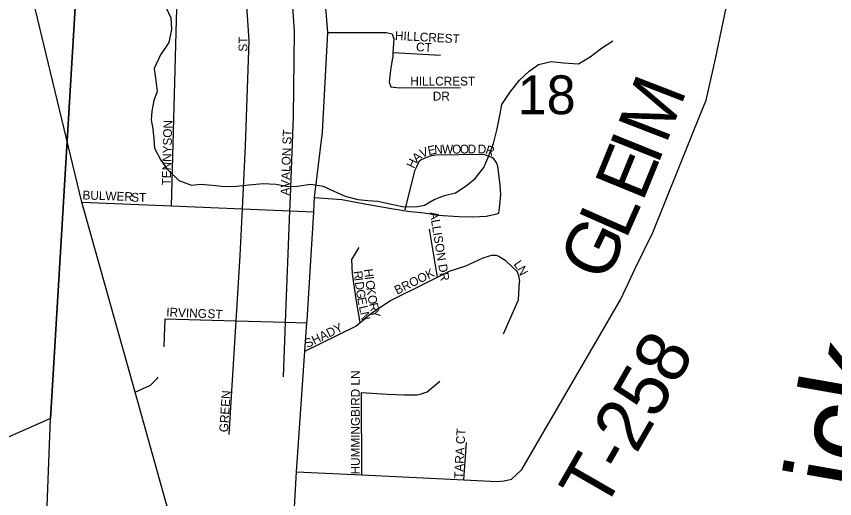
# Model space of a CAD drawing. Extents: x 1624196 to 2029251, y 146837 to 440034.
# Drawn here: x 1866006 to 1870650, y 260043 to 262784 of the extents above; entities that cross this region are included whole.
import ezdxf

# ---------------------------------------------------------------- set-up
doc = ezdxf.new("R2010")
doc.units = 0
for name, color, linetype in [('GM_X_County_Road', 7, 'Continuous'), ('GM_X_Minor_River', 7, 'Continuous'), ('GM_X_Minor_River_Text', 7, 'Continuous'), ('GM_X_Section', 7, 'Continuous'), ('GM_X_Section_Text', 7, 'Continuous'), ('GM_X_Township_Road', 7, 'Continuous'), ('GM_X_Township_Road_Text', 7, 'Continuous'), ('GM_X_Township_Subdivision', 7, 'Continuous'), ('GM_X_Township_Subdivision_Text', 7, 'Continuous')]:
    doc.layers.add(name, color=color, linetype=linetype)

msp = doc.modelspace()

# ---------------------------------------------------------------- linework, layer by layer
at = {"layer": 'GM_X_County_Road'}
for points in [[(1867016.2, 259449.3), (1866680.5, 260648), (1866378.1, 261727.9), (1865950, 263507.3), (1865868, 264025.5), (1865831.5, 264390), (1865827, 264599.6), (1865858.9, 265423.9), (1865861.6, 265586.7)], [(1867547.3, 259323.3), (1867596.2, 260196.4), (1867643.9, 260881.7), (1867655.2, 261043.1), (1867656, 261055.5), (1867693.7, 261672.7), (1867698.7, 261754.4), (1867743.6, 262126.6), (1867774.8, 262693), (1867760, 262854.7), (1867760, 263082.2), (1867749, 263347), (1867728.1, 263652), (1867689.8, 264117.9), (1867679.8, 264316.7), (1867679.8, 264377.8), (1867662.8, 264460.2), (1867586.8, 265007.1), (1867577.4, 265105.3), (1867562.6, 265135)]]:
    msp.add_lwpolyline(points, dxfattribs=at)
at = {"layer": 'GM_X_Minor_River'}
for points in [[(1866855.1, 262835.7), (1866882.6, 262775.5), (1866886.1, 262709.4), (1866871.5, 262635.4), (1866825, 262565.7), (1866788.4, 262487.9), (1866795.9, 262431.8), (1866805.4, 262357.6), (1866787, 262305.7), (1866774.5, 262245.7), (1866772.1, 262195.7), (1866781.7, 262145.6), (1866787.2, 262085.4), (1866790.8, 262035.4), (1866826.3, 261967), (1866861.8, 261914.7), (1866929.3, 261852.1), (1867001, 261825.5), (1867053, 261831.1), (1867118.9, 261824.5), (1867186.8, 261818), (1867254.8, 261819.5), (1867324.8, 261826.9), (1867406.8, 261834.3), (1867478.7, 261829.7), (1867548.6, 261817.2), (1867600.5, 261818.8), (1867676.6, 261830.2), (1867748.4, 261819.6), (1867808.2, 261791.1), (1867871.9, 261762.6), (1867943.7, 261744), (1868001.6, 261737.5), (1868057.5, 261733.1), (1868125.4, 261718.5), (1868197.2, 261703.9), (1868273.1, 261701.3), (1868323.2, 261711), (1868377.4, 261742.6), (1868435.5, 261766.1), (1868497.6, 261781.7), (1868559.9, 261821.2), (1868610.2, 261862.9), (1868658.6, 261924.6), (1868681, 261978.5), (1868713.7, 262062.3), (1868734.3, 262144.2), (1868751, 262230.2), (1868761.4, 262282.2), (1868805.9, 262351.9), (1868862.4, 262421.5), (1868916.8, 262473.1), (1868969, 262510.8), (1869041.1, 262528.2), (1869111, 262519.7), (1869196.9, 262515), (1869263.2, 262554.5), (1869327.5, 262604.1)], [(1869327.5, 262604.1), (1869391.8, 262645.6)]]:
    msp.add_lwpolyline(points, dxfattribs=at)
at = {"layer": 'GM_X_Section'}
msp.add_lwpolyline([(1863140.4, 265454.9), (1866483.9, 265233.4), (1866199.3, 260498.3), (1864651.3, 259815.2)], dxfattribs=at)
msp.add_lwpolyline([(1866483.9, 265233.4), (1871875.5, 264953), (1871606.9, 259505.4), (1866171.2, 259752), (1866199.3, 260498.3)], close=True, dxfattribs=at)
at = {"layer": 'GM_X_Township_Road'}
for points in [[(1868870.9, 260206.2), (1868874.3, 260209.4), (1869435.8, 261176.5), (1869518.9, 261352.1), (1869618.1, 261555.6), (1869894.2, 262242.5), (1869920.6, 262308.4), (1869974.1, 262542.3), (1870339.9, 264293.2), (1870370.3, 264451.8), (1870427.3, 264611.5), (1870634.5, 265099.9)], [(1867596.2, 260196.4), (1867966, 260178.2), (1868546.1, 260149.6), (1868734.1, 260140.4), (1868774, 260144.1), (1868816, 260153.8), (1868870.6, 260205.9), (1868870.9, 260206.2)]]:
    msp.add_lwpolyline(points, dxfattribs=at)
at = {"layer": 'GM_X_Township_Subdivision'}
for points in [[(1867213.3, 260408.5), (1867253.6, 261054.4), (1867276.8, 261425.1), (1867289.7, 261689.6), (1867307.1, 262048), (1867326.9, 262644.9), (1867301.3, 263047), (1867301, 263052.3), (1867300.1, 263074.1), (1867282.6, 263545.9), (1867280, 263577.6), (1867277.7, 263606), (1867229, 264210.6), (1867226.5, 264251.8), (1867167.4, 265216.6), (1867011.8, 265457.8), (1866904.4, 265630.2)], [(1867559.7, 261711.3), (1867579.1, 262214.1), (1867584.6, 262698.8), (1867557.7, 263094.4), (1867550.4, 263202.4)], [(1866915.7, 262761.4), (1866922.4, 263012.5)], [(1866887.4, 261706.5), (1866915.7, 262761.4)], [(1867774.8, 262693), (1868104.1, 262693), (1868138.7, 262684.8), (1868148.6, 262656.8), (1868143.2, 262577.9), (1868142, 262559.6), (1868130.5, 262479), (1868122.2, 262409.8), (1868132.1, 262383.5), (1868181.5, 262376.9), (1868527.3, 262380.2)], [(1868143.2, 262577.9), (1868413.7, 262564)], [(1867698.7, 261754.4), (1867854.3, 261742.9), (1868003.9, 261715.8), (1868123.6, 261694.9), (1868225.3, 261676.1), (1868321, 261667.4), (1868398.8, 261654.8), (1868516.5, 261645.9), (1868596.4, 261645.3), (1868673.2, 261648.5), (1868733.2, 261661.1), (1868743.8, 261666.4), (1868749, 261695.9), (1868755.3, 261769.6), (1868751.4, 261826.4), (1868738.1, 261930.6), (1868733.1, 261949.1), (1868726.3, 261960.8), (1868715.3, 261974.4), (1868700.5, 261983), (1868683.7, 261990.2), (1868664.7, 261997.5), (1868646.7, 261999.4), (1868387.1, 261995.3), (1868360.4, 261991.2), (1868333.1, 261981.7), (1868303.1, 261967.9), (1868290.9, 261956.5), (1868277.2, 261928.1), (1868266.7, 261906.1), (1868211.3, 261684.2)], [(1866378.1, 261727.9), (1866887.4, 261706.5), (1867289.7, 261689.6), (1867558.5, 261678.4), (1867693.7, 261672.7)], [(1867522.2, 260736), (1867534.1, 261046.5), (1867558.5, 261678.4), (1867559.7, 261711.3)], [(1868396.8, 261302.1), (1868350.7, 261575.4)], [(1867956.6, 261044.1), (1867935, 261176.7), (1867913.6, 261321.8), (1867909.4, 261402.8), (1867952, 261471)], [(1867985.9, 261068.4), (1868018.8, 261095.8), (1868128.7, 261169.5), (1868340.4, 261273.6), (1868396.8, 261302.1), (1868468.8, 261338.6), (1868557.5, 261365.6), (1868655.4, 261412.5), (1868690.9, 261424.1), (1868704.8, 261427.3), (1868726.7, 261427.3), (1868745.3, 261421.9), (1868779.5, 261398.7), (1868826.2, 261355.6), (1868846.6, 261335.5), (1868856.1, 261313.4), (1868862, 261277.4)], [(1868770.9, 260980.5), (1868834.9, 261125.5), (1868856.2, 261172.4), (1868862, 261277.4)], [(1866845.6, 260907), (1866847.3, 260965.9), (1866850.1, 261065.8)], [(1866850.1, 261065.8), (1867252.6, 261054.5)], [(1867643.9, 260881.7), (1867932.1, 261023.7), (1867956.6, 261044.1), (1867985.1, 261067.8), (1867985.9, 261068.4)], [(1867252.6, 261054.5), (1867253.6, 261054.4), (1867534.1, 261046.5), (1867655.2, 261043.1)], [(1866680.5, 260648), (1866768.2, 260687.7), (1866805.6, 260725.6), (1866810.3, 260733.5)], [(1867965.8, 260646.7), (1868110.8, 260638.1), (1868208.9, 260633.9), (1868281.4, 260633.9), (1868298, 260636.6), (1868336.8, 260650.9), (1868409.3, 260710.6)], [(1867966, 260178.2), (1867965.8, 260646.7)], [(1868546.1, 260149.6), (1868560.8, 260363)]]:
    msp.add_lwpolyline(points, dxfattribs=at)

# ---------------------------------------------------------------- texts
at = {"layer": 'GM_X_Minor_River_Text'}
msp.add_text('Lick', height=499.99, rotation=80.0008, dxfattribs=at).set_placement((1870798.3, 259702.6))
at = {"layer": 'GM_X_Section_Text'}
msp.add_text('18', height=221, rotation=0, dxfattribs=at).set_placement((1868851.4, 262227.6))
at = {"layer": 'GM_X_Township_Road_Text'}
for s, rotation, p in [('M', 68.8495, (1869692.7, 262051.8)), ('I', 68.0248, (1869644.9, 261933.2)), ('E', 67.77, (1869559.4, 261724.1)), ('L', 66.1225, (1869464.9, 261510.2)), ('G', 64.2951, (1869346, 261262.9)), ('T-258', 60.0461, (1869335.5, 259965.3))]:
    msp.add_text(s, height=300, rotation=rotation, dxfattribs=at).set_placement(p)
at = {"layer": 'GM_X_Township_Subdivision_Text'}
for s, rotation, p in [('HILLCREST', 356.9474, (1868153.8, 262650.3)), ('ST', 90, (1867317.4, 262583.6)), ('CT', 356.8222, (1868273.6, 262586.3)), ('HILLCREST', 0, (1868242, 262390.7)), ('DR', 0, (1868369.6, 262305.6)), ('TENNYSON', 88.4733, (1866881.8, 261822.7)), ('AVALON ST', 87.7986, (1867555, 261765.6)), ('V', 22.1424, (1868308.1, 261978.8)), ('E', 12.194, (1868346.7, 261994.7)), ('N', 2.7445, (1868378.9, 262001.8)), ('W', 0.4959, (1868422.4, 262003.9)), ('O', 0.3388, (1868479.5, 262004.4)), ('O', 0.3362, (1868523.5, 262004.7)), ('D', 0.3388, (1868567.5, 262004.9)), ('D', 359.4972, (1868624.5, 262005.3)), ('R', 340.5553, (1868664.2, 262005.7)), ('A', 41.9385, (1868279.2, 261951.8)), ('H', 64.2463, (1868263.2, 261916.2)), ('BULWER', 358.0578, (1866381.1, 261743.9)), ('ST', 0, (1866658, 261730.7)), ('ALLISON DR', 279.1183, (1868352.4, 261669.9)), ('L', 306.5175, (1868825.8, 261375)), ('H', 277.5398, (1867978.6, 261346.6)), ('BROOK', 26.565, (1868167.4, 261201.7)), ('N', 298.2319, (1868845.8, 261348.3)), ('R', 277.1582, (1867919.4, 261335)), ('I', 277.144, (1867924.4, 261295.7)), ('I', 277.5467, (1867984.4, 261303)), ('D', 277.4684, (1867927.2, 261273.5)), ('C', 277.5256, (1867987.3, 261281.2)), ('G', 279.2175, (1867933.1, 261228.3)), ('K', 277.5304, (1867992.5, 261242)), ('E', 280.644, (1867940.4, 261183.5)), ('O', 280.8558, (1867998.7, 261195.2)), ('R', 282.3556, (1868007.3, 261150.6)), ('IRVING', 357.6617, (1866856.4, 261079.4)), ('ST', 356.4262, (1867089.7, 261070.6)), ('L', 282.2446, (1867949.9, 261134.5)), ('Y', 282.3344, (1868015.8, 261111.9)), ('N', 282.3139, (1867957.4, 261100)), ('SHADY', 26.0299, (1867657, 260898.1)), ('HUMMINGBIRD LN', 90, (1867955.3, 260181.2)), ('GREEN', 86.266, (1867207.4, 260419.5)), ('TARA CT', 87.0908, (1868540.6, 260155.3))]:
    msp.add_text(s, height=50, rotation=rotation, dxfattribs=at).set_placement(p)

doc.saveas('drawing.dxf')
